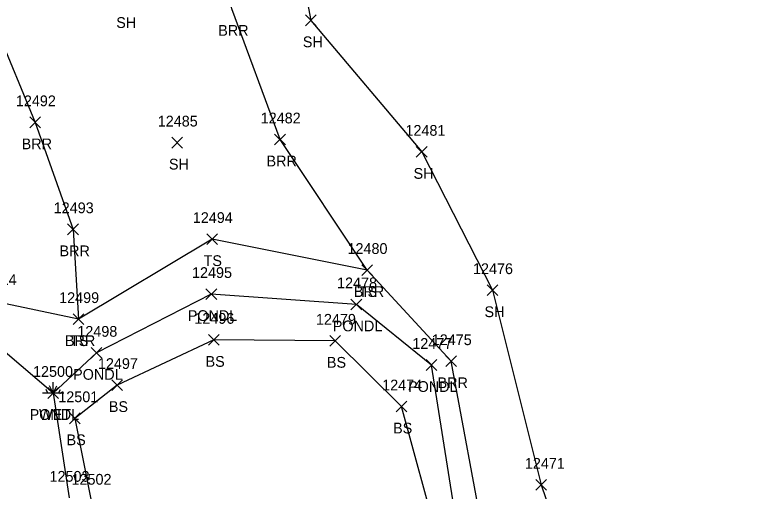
# Model space of a CAD drawing. Extents: x 1439173 to 1457902, y 641926 to 659889.
# Drawn here: x 1447721.4 to 1447857.3, y 649879.1 to 649967.8 of the extents above; entities that cross this region are included whole.
import ezdxf

# ---------------------------------------------------------------- set-up
doc = ezdxf.new("R2010")
doc.units = 0
for name, color, linetype in [('L_A', 7, 'Continuous'), ('L_I', 7, 'Continuous'), ('L_TIC', 7, 'Continuous'), ('LABL', 7, 'Continuous'), ('LAWE', 7, 'Continuous'), ('LELB', 7, 'Continuous'), ('LSOGP', 7, 'Continuous'), ('LWET', 7, 'Continuous')]:
    doc.layers.add(name, color=color, linetype=linetype)

msp = doc.modelspace()

# ---------------------------------------------------------------- linework, layer by layer
at = {"layer": 'L_TIC'}
for points in [[(1447775.52, 649965.69), (1447777.52, 649967.69)], [(1447777.52, 649965.69), (1447775.52, 649967.69)], [(1447724.23, 649946.72), (1447726.23, 649948.72)], [(1447726.23, 649946.72), (1447724.23, 649948.72)], [(1447750.62, 649942.95), (1447752.62, 649944.95)], [(1447752.62, 649942.95), (1447750.62, 649944.95)], [(1447769.77, 649943.53), (1447771.77, 649945.53)], [(1447771.77, 649943.53), (1447769.77, 649945.53)], [(1447796.12, 649941.23), (1447798.12, 649943.23)], [(1447798.12, 649941.23), (1447796.12, 649943.23)], [(1447731.27, 649926.83), (1447733.27, 649928.83)], [(1447733.27, 649926.83), (1447731.27, 649928.83)], [(1447757.14, 649925.01), (1447759.14, 649927.01)], [(1447759.14, 649925.01), (1447757.14, 649927.01)], [(1447786, 649919.26), (1447788, 649921.26)], [(1447788, 649919.26), (1447786, 649921.26)], [(1447786, 649919.26), (1447788, 649921.26)], [(1447788, 649919.26), (1447786, 649921.26)], [(1447809.31, 649915.51), (1447811.31, 649917.51)], [(1447811.31, 649915.51), (1447809.31, 649917.51)], [(1447756.99, 649914.79), (1447758.99, 649916.79)], [(1447758.99, 649914.79), (1447756.99, 649916.79)], [(1447783.97, 649912.87), (1447785.97, 649914.87)], [(1447785.97, 649912.87), (1447783.97, 649914.87)], [(1447732.29, 649910.13), (1447734.29, 649912.13)], [(1447734.29, 649910.13), (1447732.29, 649912.13)], [(1447732.29, 649910.13), (1447734.29, 649912.13)], [(1447734.29, 649910.13), (1447732.29, 649912.13)], [(1447757.48, 649906.27), (1447759.48, 649908.27)], [(1447759.48, 649906.27), (1447757.48, 649908.27)], [(1447780.05, 649906.1), (1447782.05, 649908.1)], [(1447782.05, 649906.1), (1447780.05, 649908.1)], [(1447735.66, 649903.86), (1447737.66, 649905.86)], [(1447737.66, 649903.86), (1447735.66, 649905.86)], [(1447801.58, 649902.3), (1447803.58, 649904.3)], [(1447803.58, 649902.3), (1447801.58, 649904.3)], [(1447797.96, 649901.6), (1447799.96, 649903.6)], [(1447799.96, 649901.6), (1447797.96, 649903.6)], [(1447739.49, 649897.87), (1447741.49, 649899.87)], [(1447741.49, 649897.87), (1447739.49, 649899.87)], [(1447727.59, 649896.4), (1447729.59, 649898.4)], [(1447729.59, 649896.4), (1447727.59, 649898.4)], [(1447792.36, 649893.88), (1447794.36, 649895.88)], [(1447794.36, 649893.88), (1447792.36, 649895.88)], [(1447731.63, 649891.69), (1447733.63, 649893.69)], [(1447733.63, 649891.69), (1447731.63, 649893.69)], [(1447818.33, 649879.32), (1447820.33, 649881.32)], [(1447820.33, 649879.32), (1447818.33, 649881.32)]]:
    msp.add_lwpolyline(points, dxfattribs=at)
at = {"layer": 'LABL'}
for points in [[(1447839.97, 649764.21), (1447831.35, 649818.5), (1447821.53, 649847.83), (1447808.88, 649869.61), (1447802.58, 649903.3), (1447787, 649920.26), (1447770.77, 649944.53), (1447761.79, 649968.82), (1447755.13, 650001.32), (1447731.91, 649996.86), (1447719.7, 649996.24)], [(1447717.93, 649965.28), (1447725.23, 649947.72), (1447732.27, 649927.83), (1447733.29, 649911.13), (1447717.36, 649914.49)]]:
    msp.add_lwpolyline(points, dxfattribs=at)
at = {"layer": 'LAWE'}
msp.add_lwpolyline([(1447736.75, 649850.03), (1447746.26, 649836.01), (1447762.55, 649823.14), (1447781.14, 649825.3), (1447795.91, 649842.22), (1447804.27, 649868.94), (1447798.96, 649902.6), (1447784.97, 649913.87), (1447757.99, 649915.79), (1447736.66, 649904.86), (1447728.59, 649897.4), (1447731.57, 649877.9)], dxfattribs=at)
at = {"layer": 'LELB'}
for points in [[(1447787, 649920.26), (1447758.14, 649926.01), (1447733.29, 649911.13)], [(1447741.88, 649853.02), (1447749.61, 649839.6), (1447763.68, 649828.14), (1447778.1, 649829.9), (1447791.43, 649842.74), (1447800.27, 649869.72), (1447793.36, 649894.88), (1447781.05, 649907.1), (1447758.48, 649907.27), (1447740.49, 649898.87), (1447732.63, 649892.69), (1447735.66, 649877.35)]]:
    msp.add_lwpolyline(points, dxfattribs=at)
at = {"layer": 'LSOGP'}
msp.add_lwpolyline([(1447619.03, 650360.07), (1447637.42, 650315.88), (1447658.67, 650267.12), (1447673.57, 650226.26), (1447688.13, 650176.69), (1447711.15, 650147.55), (1447725.49, 650099.49), (1447742.44, 650053.11), (1447746.12, 650031.62), (1447770.15, 650000.07), (1447776.52, 649966.69), (1447797.12, 649942.22), (1447810.31, 649916.5), (1447819.33, 649880.31), (1447829.59, 649850.37), (1447834.46, 649819.36), (1447847.14, 649760.71), (1447857.32, 649718.69)], dxfattribs=at)
at = {"layer": 'LWET'}
for p, q in [((1447728.59, 649897.4), (1447727.92, 649898.74)), ((1447728.59, 649897.4), (1447728.59, 649899.4)), ((1447728.59, 649897.4), (1447729.25, 649898.74)), ((1447730.59, 649897.4), (1447726.59, 649897.4)), ((1447727.59, 649897.4), (1447727.25, 649898.07)), ((1447729.59, 649897.4), (1447729.92, 649898.07))]:
    msp.add_line(p, q, dxfattribs=at)
msp.add_lwpolyline([(1447728.59, 649897.4), (1447714.06, 649909.71), (1447704.38, 649923.22), (1447696.17, 649922.83), (1447694.35, 649933.98)], dxfattribs=at)

# ---------------------------------------------------------------- texts
at = {"layer": 'L_A'}
for s, p in [('SH', (1447740.31, 649965.28)), ('BRR', (1447759.28, 649963.82)), ('SH', (1447775.01, 649961.69)), ('BRR', (1447722.72, 649942.72)), ('SH', (1447750.11, 649938.95)), ('BRR', (1447768.26, 649939.53)), ('SH', (1447795.61, 649937.23)), ('BRR', (1447729.76, 649922.83)), ('TS', (1447756.55, 649921.01)), ('BRR', (1447784.49, 649915.26)), ('TS', (1447785.41, 649915.26)), ('SH', (1447808.8, 649911.51)), ('PONDL', (1447753.61, 649910.79)), ('PONDL', (1447780.59, 649908.87)), ('BRR', (1447730.77, 649906.13)), ('TS', (1447731.7, 649906.13)), ('BS', (1447756.92, 649902.27)), ('BS', (1447779.49, 649902.1)), ('PONDL', (1447732.29, 649899.86)), ('PONDL', (1447794.58, 649897.6)), ('BRR', (1447800.07, 649898.3)), ('BS', (1447738.93, 649893.87)), ('PONDL', (1447724.21, 649892.4)), ('WET', (1447725.96, 649892.4)), ('BS', (1447791.8, 649889.88)), ('BS', (1447731.07, 649887.69))]:
    msp.add_text(s, height=2, dxfattribs=at).set_placement(p)
at = {"layer": 'L_I'}
for s, p in [('12492', (1447721.64, 649950.72)), ('12485', (1447748.03, 649946.95)), ('12482', (1447767.18, 649947.53)), ('12481', (1447794.1, 649945.23)), ('12493', (1447728.68, 649930.83)), ('12494', (1447754.55, 649929.01)), ('12480', (1447783.32, 649923.26)), ('12480', (1447783.32, 649923.26)), ('12476', (1447806.66, 649919.51)), ('12495', (1447754.4, 649918.79)), ('12514', (1447714.34, 649917.49)), ('12478', (1447781.38, 649916.87)), ('12499', (1447729.69, 649914.13)), ('12499', (1447729.69, 649914.13)), ('12496', (1447754.84, 649910.27)), ('12479', (1447777.45, 649910.1)), ('12498', (1447733.07, 649907.86)), ('12475', (1447798.99, 649906.3)), ('12477', (1447795.37, 649905.6)), ('12497', (1447736.9, 649901.87)), ('12500', (1447724.83, 649900.4)), ('12500', (1447724.83, 649900.4)), ('12474', (1447789.77, 649897.88)), ('12501', (1447729.53, 649895.69)), ('12471', (1447816.31, 649883.32)), ('12503', (1447727.9, 649880.9)), ('12503', (1447727.9, 649880.9)), ('12502', (1447731.99, 649880.35)), ('12502', (1447731.99, 649880.35))]:
    msp.add_text(s, height=2, dxfattribs=at).set_placement(p)

doc.saveas('drawing.dxf')
